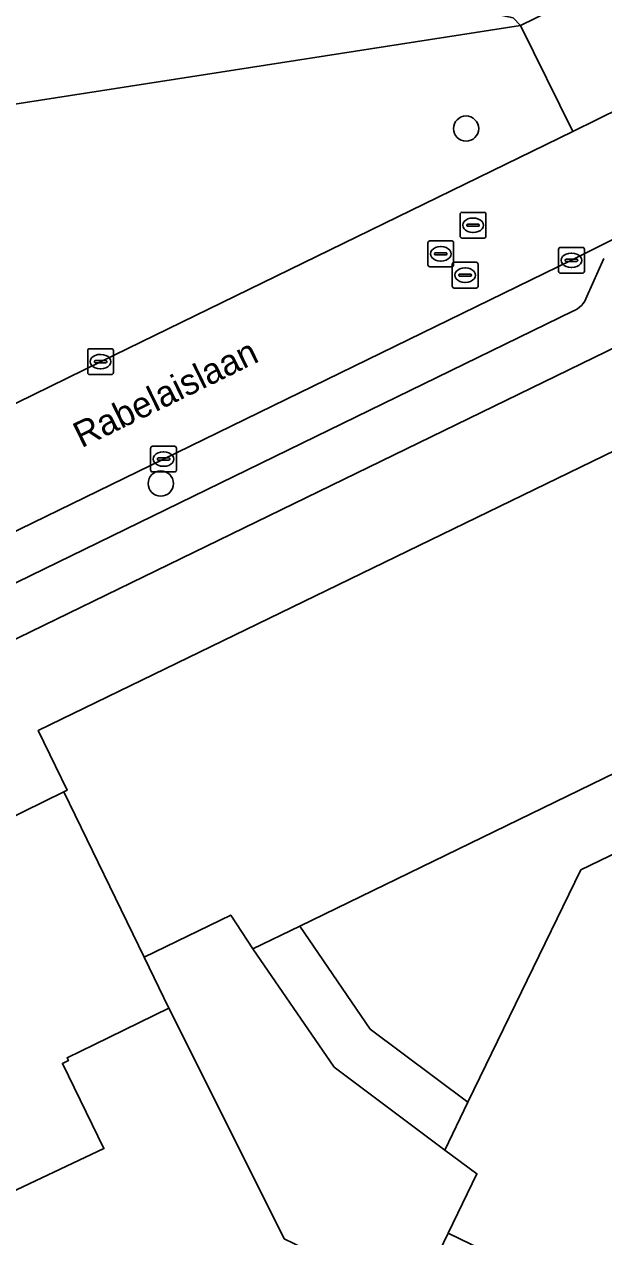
# Model space of a CAD drawing. Extents: x 160455 to 162082, y 388339 to 389736.
# Drawn here: x 160679.78 to 160702.27, y 388992.54 to 389039.61 of the extents above; entities that cross this region are included whole.
import ezdxf

# ---------------------------------------------------------------- set-up
doc = ezdxf.new("R2010")
doc.units = 0
for name, color, linetype in [('IMGEO_Boom', 7, 'Continuous'), ('IMGEO_Erf', 7, 'Continuous'), ('IMGEO_Groenvoorziening', 7, 'Continuous'), ('IMGEO_Kolk', 7, 'Continuous'), ('IMGEO_Openbare_ruimte_label', 7, 'Continuous'), ('IMGEO_Pand', 7, 'Continuous'), ('IMGEO_Pand_overbouw', 7, 'Continuous'), ('IMGEO_Parkeervlak_open', 7, 'Continuous'), ('IMGEO_Rijbaan_lokaal_gesloten', 7, 'Continuous'), ('IMGEO_Rioolput', 7, 'Continuous'), ('IMGEO_Voetpad_open', 7, 'Continuous')]:
    doc.layers.add(name, color=color, linetype=linetype)

msp = doc.modelspace()

# ---------------------------------------------------------------- linework, layer by layer
at = {"layer": 'IMGEO_Boom'}
for centre in [(160696.929, 389035.555), (160685.078, 389021.776)]:
    msp.add_circle(centre, 0.489, dxfattribs=at)
at = {"layer": 'IMGEO_Erf'}
for points in [[(160631.304, 389134.452), (160635.49, 389126.227), (160661.981, 389074.172), (160677.134, 389044.454), (160698.752, 389039.86), (160699.042, 389039.553), (160715.037, 389047.378)], [(160706.578, 389028.939), (160704.8, 389028.074), (160674.691, 389013.432), (160651.38, 389002.026)], [(160677.377, 389007.887), (160681.311, 389009.806), (160681.445, 389009.872), (160680.32, 389012.188), (160708.539, 389025.895)], [(160702.742, 389010.556), (160690.481, 389004.601), (160688.649, 389003.711), (160687.793, 389005.025), (160684.429, 389003.39), (160685.392, 389001.409), (160682.501, 389000), (160681.444, 388999.485), (160681.496, 388999.377), (160681.263, 388999.267), (160682.873, 388995.963), (160678.759, 388994.027), (160677.143, 388997.327), (160677.049, 388997.283), (160675.92, 388996.752), (160673.367, 388995.55), (160673.42, 388995.442), (160669.095, 388993.334), (160667.611, 388996.387), (160667.455, 388996.311), (160664.308, 388994.778), (160663.857, 388994.558), (160665.343, 388991.507)], [(160704.929, 388988.463), (160696.232, 388992.673), (160697.352, 388994.987), (160696.098, 388995.905), (160697.002, 388997.764), (160701.389, 389006.781), (160703.963, 389008.022)]]:
    msp.add_lwpolyline(points, dxfattribs=at)
at = {"layer": 'IMGEO_Groenvoorziening'}
for points in [[(160699.042, 389039.553), (160698.752, 389039.86), (160677.134, 389044.454), (160668.93, 389041.037), (160672.353, 389034.231), (160678.648, 389036.386)], [(160701.076, 389035.437), (160699.042, 389039.553), (160678.648, 389036.386), (160672.353, 389034.231), (160677.522, 389023.953), (160682.743, 389026.507)]]:
    msp.add_lwpolyline(points, close=True, dxfattribs=at)
at = {"layer": 'IMGEO_Kolk'}
for p, q in [((160700.519, 389030.016), (160700.519, 389030.868)), ((160700.594, 389030.942), (160701.446, 389030.942)), ((160701.52, 389030.868), (160701.52, 389030.016)), ((160700.778, 389030.436), (160700.778, 389030.448)), ((160701.216, 389030.399), (160700.818, 389030.399)), ((160700.821, 389030.485), (160701.219, 389030.485)), ((160701.007, 389030.722), (160701.032, 389030.722)), ((160701.262, 389030.448), (160701.262, 389030.436)), ((160701.446, 389029.942), (160700.594, 389029.942)), ((160701.03, 389030.162), (160701.005, 389030.162)), ((160682.242, 389026.083), (160682.242, 389026.935)), ((160682.317, 389027.009), (160683.169, 389027.009)), ((160682.73, 389026.789), (160682.755, 389026.789)), ((160683.243, 389026.935), (160683.243, 389026.083)), ((160682.501, 389026.503), (160682.501, 389026.515)), ((160682.939, 389026.466), (160682.541, 389026.466)), ((160682.544, 389026.552), (160682.942, 389026.552)), ((160682.753, 389026.229), (160682.728, 389026.229)), ((160682.985, 389026.515), (160682.985, 389026.503)), ((160683.169, 389026.009), (160682.317, 389026.009)), ((160684.686, 389022.3), (160684.686, 389023.152)), ((160684.761, 389023.226), (160685.613, 389023.226)), ((160685.174, 389023.006), (160685.199, 389023.006)), ((160685.687, 389023.152), (160685.687, 389022.3)), ((160684.945, 389022.72), (160684.945, 389022.732)), ((160685.383, 389022.683), (160684.985, 389022.683)), ((160684.988, 389022.769), (160685.386, 389022.769)), ((160685.197, 389022.446), (160685.172, 389022.446)), ((160685.429, 389022.732), (160685.429, 389022.72)), ((160685.613, 389022.226), (160684.761, 389022.226))]:
    msp.add_line(p, q, dxfattribs=at)
for points in [[(160700.519, 389030.016), (160700.519, 389030.868)], [(160700.594, 389030.942), (160701.446, 389030.942)], [(160701.52, 389030.868), (160701.52, 389030.016)], [(160701.446, 389029.942), (160700.594, 389029.942)], [(160682.242, 389026.083), (160682.242, 389026.935)], [(160682.317, 389027.009), (160683.169, 389027.009)], [(160683.243, 389026.935), (160683.243, 389026.083)], [(160683.169, 389026.009), (160682.317, 389026.009)], [(160684.686, 389022.3), (160684.686, 389023.152)], [(160684.761, 389023.226), (160685.613, 389023.226)], [(160685.687, 389023.152), (160685.687, 389022.3)], [(160685.613, 389022.226), (160684.761, 389022.226)]]:
    msp.add_lwpolyline(points, dxfattribs=at)
for centre, radius, start, end in [((160700.596, 389030.866), 0.0765, 91.552, 178.448), ((160700.596, 389030.866), 0.0765, 91.552, 178.448), ((160701.444, 389030.866), 0.0765, 1.552, 88.448), ((160701.444, 389030.866), 0.0765, 1.552, 88.448), ((160700.818, 389030.445), 0.0403, 85.8775, 175.7526), ((160700.815, 389030.435), 0.0366, 178.938, 274.7102), ((160701.219, 389030.442), 0.043, 264.8664, 352.4533), ((160701.223, 389030.447), 0.0386, 1.7309, 96.639), ((160700.596, 389030.018), 0.0765, 181.552, 268.448), ((160700.596, 389030.018), 0.0765, 181.552, 268.448), ((160701.444, 389030.018), 0.0765, 271.552, 358.448), ((160701.444, 389030.018), 0.0765, 271.552, 358.448), ((160682.319, 389026.933), 0.0765, 91.552, 178.448), ((160682.319, 389026.933), 0.0765, 91.552, 178.448), ((160683.167, 389026.933), 0.0765, 1.552, 88.448), ((160683.167, 389026.933), 0.0765, 1.552, 88.448), ((160682.541, 389026.512), 0.0403, 85.8775, 175.7526), ((160682.538, 389026.502), 0.0366, 178.938, 274.7102), ((160682.942, 389026.509), 0.043, 264.8664, 352.4533), ((160682.946, 389026.514), 0.0386, 1.7309, 96.639), ((160682.319, 389026.085), 0.0765, 181.552, 268.448), ((160682.319, 389026.085), 0.0765, 181.552, 268.448), ((160683.167, 389026.085), 0.0765, 271.552, 358.448), ((160683.167, 389026.085), 0.0765, 271.552, 358.448), ((160684.763, 389023.15), 0.0765, 91.552, 178.448), ((160684.763, 389023.15), 0.0765, 91.552, 178.448), ((160685.611, 389023.15), 0.0765, 1.552, 88.448), ((160685.611, 389023.15), 0.0765, 1.552, 88.448), ((160684.985, 389022.729), 0.0403, 85.8775, 175.7526), ((160684.982, 389022.719), 0.0366, 178.938, 274.7102), ((160685.386, 389022.726), 0.043, 264.8664, 352.4533), ((160685.39, 389022.731), 0.0386, 1.7309, 96.639), ((160684.763, 389022.302), 0.0765, 181.552, 268.448), ((160684.763, 389022.302), 0.0765, 181.552, 268.448), ((160685.611, 389022.302), 0.0765, 271.552, 358.448), ((160685.611, 389022.302), 0.0765, 271.552, 358.448)]:
    msp.add_arc(centre, radius, start, end, dxfattribs=at)
for centre, major_axis, ratio, start_param, end_param in [((160701.006, 389030.442), (-0.387, 0.002), 0.722429, 4.712389, 7.853982), ((160701.031, 389030.442), (-0.39, 0.002), 0.717154, 1.570796, 4.712389), ((160682.729, 389026.509), (-0.387, 0.002), 0.722429, 4.712389, 7.853982), ((160682.754, 389026.509), (-0.39, 0.002), 0.717154, 1.570796, 4.712389), ((160685.173, 389022.726), (-0.387, 0.002), 0.722429, 4.712389, 7.853982), ((160685.198, 389022.726), (-0.39, 0.002), 0.717154, 1.570796, 4.712389)]:
    msp.add_ellipse(centre, major_axis=major_axis, ratio=ratio, start_param=start_param, end_param=end_param, dxfattribs=at)
at = {"layer": 'IMGEO_Pand'}
for points in [[(160708.539, 389025.895), (160680.32, 389012.188), (160681.445, 389009.872), (160681.311, 389009.806), (160684.429, 389003.39), (160687.793, 389005.025), (160688.649, 389003.711), (160690.481, 389004.601), (160702.742, 389010.556)], [(160703.963, 389008.022), (160701.389, 389006.781), (160697.002, 388997.764), (160696.098, 388995.905), (160697.352, 388994.987), (160696.232, 388992.673), (160704.929, 388988.463)]]:
    msp.add_lwpolyline(points, dxfattribs=at)
msp.add_lwpolyline([(160684.429, 389003.39), (160681.311, 389009.806), (160677.377, 389007.887), (160676.85, 389008.967), (160672.516, 389006.856), (160673.039, 389005.779), (160675.845, 389000), (160677.143, 388997.327), (160678.759, 388994.027), (160682.873, 388995.963), (160681.263, 388999.267), (160681.496, 388999.377), (160681.444, 388999.485), (160682.501, 389000), (160685.392, 389001.409)], close=True, dxfattribs=at)
at = {"layer": 'IMGEO_Pand_overbouw'}
for points in [[(160684.429, 389003.39), (160685.392, 389001.409), (160686.098, 389000), (160689.872, 388992.464), (160690.248, 388992.282), (160694.941, 388990.006), (160696.232, 388992.673), (160704.929, 388988.463), (160710.543, 389000), (160710.81, 389000.549), (160710.52, 389000.682), (160710.382, 389000.382), (160709.341, 389002.516), (160712.043, 389003.818), (160711.916, 389003.546), (160712.208, 389003.41), (160712.515, 389004.079), (160717.865, 389006.688), (160708.539, 389025.895), (160680.32, 389012.188), (160681.445, 389009.872), (160681.311, 389009.806)], [(160688.649, 389003.711), (160691.804, 388999.127), (160696.098, 388995.905), (160697.002, 388997.764), (160693.202, 389000.599), (160690.481, 389004.601)]]:
    msp.add_lwpolyline(points, close=True, dxfattribs=at)
at = {"layer": 'IMGEO_Parkeervlak_open'}
for points in [[(160703.094, 389031.478), (160701.02, 389030.443), (160685.186, 389022.728), (160677.049, 389018.758), (160677.836, 389017.143), (160678.425, 389017.43), (160701.072, 389028.47)], [(160701.616, 389029.041), (160702.272, 389030.518)]]:
    msp.add_lwpolyline(points, dxfattribs=at)
msp.add_arc((160700.763, 389029.309), 0.895, 290.2358, 342.5385, dxfattribs=at)
at = {"layer": 'IMGEO_Rijbaan_lokaal_gesloten'}
msp.add_lwpolyline([(160714.541, 389042.026), (160702.958, 389036.375), (160701.076, 389035.437), (160682.743, 389026.507), (160677.522, 389023.953), (160676.085, 389023.25), (160666.163, 389018.396), (160649.541, 389010.262), (160648.994, 389010.023), (160650.975, 389005.988), (160651.2, 389006.091), (160657.413, 389009.132), (160661.027, 389010.901), (160665.679, 389013.179), (160668.435, 389014.528), (160669.054, 389014.834), (160673.065, 389016.814), (160673.354, 389016.955), (160677.049, 389018.758), (160685.186, 389022.728), (160701.02, 389030.443), (160703.094, 389031.478), (160703.377, 389031.619), (160720.813, 389040.138)], dxfattribs=at)
at = {"layer": 'IMGEO_Rioolput'}
for p, q in [((160696.698, 389031.378), (160696.698, 389032.23)), ((160696.773, 389032.304), (160697.625, 389032.304)), ((160697.699, 389032.23), (160697.699, 389031.378)), ((160696.957, 389031.798), (160696.957, 389031.81)), ((160697.395, 389031.761), (160696.997, 389031.761)), ((160697, 389031.847), (160697.398, 389031.847)), ((160697.186, 389032.084), (160697.211, 389032.084)), ((160697.441, 389031.81), (160697.441, 389031.798)), ((160697.625, 389031.304), (160696.773, 389031.304)), ((160697.209, 389031.524), (160697.184, 389031.524)), ((160695.445, 389030.267), (160695.445, 389031.119)), ((160695.52, 389031.193), (160696.372, 389031.193)), ((160695.933, 389030.973), (160695.958, 389030.973)), ((160696.446, 389031.119), (160696.446, 389030.267)), ((160695.704, 389030.687), (160695.704, 389030.699)), ((160696.142, 389030.65), (160695.744, 389030.65)), ((160695.747, 389030.736), (160696.145, 389030.736)), ((160695.956, 389030.413), (160695.931, 389030.413)), ((160696.188, 389030.699), (160696.188, 389030.687)), ((160696.467, 389030.366), (160697.319, 389030.366)), ((160696.372, 389030.193), (160695.52, 389030.193)), ((160696.392, 389029.44), (160696.392, 389030.292)), ((160696.651, 389029.86), (160696.651, 389029.872)), ((160696.694, 389029.909), (160697.092, 389029.909)), ((160696.88, 389030.146), (160696.905, 389030.146)), ((160697.135, 389029.872), (160697.135, 389029.86)), ((160697.393, 389030.292), (160697.393, 389029.44)), ((160697.089, 389029.823), (160696.691, 389029.823)), ((160696.903, 389029.586), (160696.878, 389029.586)), ((160697.319, 389029.366), (160696.467, 389029.366))]:
    msp.add_line(p, q, dxfattribs=at)
for points in [[(160696.698, 389031.378), (160696.698, 389032.23)], [(160696.773, 389032.304), (160697.625, 389032.304)], [(160697.699, 389032.23), (160697.699, 389031.378)], [(160697.625, 389031.304), (160696.773, 389031.304)], [(160695.445, 389030.267), (160695.445, 389031.119)], [(160695.52, 389031.193), (160696.372, 389031.193)], [(160696.446, 389031.119), (160696.446, 389030.267)], [(160696.467, 389030.366), (160697.319, 389030.366)], [(160696.372, 389030.193), (160695.52, 389030.193)], [(160696.392, 389029.44), (160696.392, 389030.292)], [(160697.393, 389030.292), (160697.393, 389029.44)], [(160697.319, 389029.366), (160696.467, 389029.366)]]:
    msp.add_lwpolyline(points, dxfattribs=at)
for centre, radius, start, end in [((160696.775, 389032.228), 0.0765, 91.552, 178.448), ((160696.775, 389032.228), 0.0765, 91.552, 178.448), ((160697.623, 389032.228), 0.0765, 1.552, 88.448), ((160697.623, 389032.228), 0.0765, 1.552, 88.448), ((160696.997, 389031.807), 0.0403, 85.8775, 175.7526), ((160696.994, 389031.797), 0.0366, 178.938, 274.7102), ((160697.398, 389031.804), 0.043, 264.8664, 352.4533), ((160697.402, 389031.809), 0.0386, 1.7309, 96.639), ((160696.775, 389031.38), 0.0765, 181.552, 268.448), ((160696.775, 389031.38), 0.0765, 181.552, 268.448), ((160697.623, 389031.38), 0.0765, 271.552, 358.448), ((160697.623, 389031.38), 0.0765, 271.552, 358.448), ((160695.522, 389031.117), 0.0765, 91.552, 178.448), ((160695.522, 389031.117), 0.0765, 91.552, 178.448), ((160696.37, 389031.117), 0.0765, 1.552, 88.448), ((160696.37, 389031.117), 0.0765, 1.552, 88.448), ((160695.744, 389030.696), 0.0403, 85.8775, 175.7526), ((160695.741, 389030.686), 0.0366, 178.938, 274.7102), ((160696.145, 389030.693), 0.043, 264.8664, 352.4533), ((160696.149, 389030.698), 0.0386, 1.7309, 96.639), ((160696.469, 389030.29), 0.0765, 91.552, 178.448), ((160696.469, 389030.29), 0.0765, 91.552, 178.448), ((160697.317, 389030.29), 0.0765, 1.552, 88.448), ((160697.317, 389030.29), 0.0765, 1.552, 88.448), ((160695.522, 389030.269), 0.0765, 181.552, 268.448), ((160695.522, 389030.269), 0.0765, 181.552, 268.448), ((160696.37, 389030.269), 0.0765, 271.552, 358.448), ((160696.37, 389030.269), 0.0765, 271.552, 358.448), ((160696.691, 389029.869), 0.0403, 85.8775, 175.7526), ((160697.096, 389029.871), 0.0386, 1.7309, 96.639), ((160696.469, 389029.442), 0.0765, 181.552, 268.448), ((160696.469, 389029.442), 0.0765, 181.552, 268.448), ((160696.688, 389029.859), 0.0366, 178.938, 274.7102), ((160697.092, 389029.866), 0.043, 264.8664, 352.4533), ((160697.317, 389029.442), 0.0765, 271.552, 358.448), ((160697.317, 389029.442), 0.0765, 271.552, 358.448)]:
    msp.add_arc(centre, radius, start, end, dxfattribs=at)
for centre, major_axis, ratio, start_param, end_param in [((160697.185, 389031.804), (-0.387, 0.002), 0.722429, 4.712389, 7.853982), ((160697.21, 389031.804), (-0.39, 0.002), 0.717154, 1.570796, 4.712389), ((160695.932, 389030.693), (-0.387, 0.002), 0.722429, 4.712389, 7.853982), ((160695.957, 389030.693), (-0.39, 0.002), 0.717154, 1.570796, 4.712389), ((160696.879, 389029.866), (-0.387, 0.002), 0.722429, 4.712389, 7.853982), ((160696.904, 389029.866), (-0.39, 0.002), 0.717154, 1.570796, 4.712389)]:
    msp.add_ellipse(centre, major_axis=major_axis, ratio=ratio, start_param=start_param, end_param=end_param, dxfattribs=at)
at = {"layer": 'IMGEO_Voetpad_open'}
for points in [[(160715.037, 389047.378), (160699.042, 389039.553), (160701.076, 389035.437), (160702.958, 389036.375), (160714.541, 389042.026)], [(160702.272, 389030.518), (160701.616, 389029.041)], [(160701.072, 389028.47), (160678.425, 389017.43), (160678.907, 389016.441), (160674.306, 389014.198), (160673.824, 389015.187), (160670.3, 389013.45), (160670.78, 389012.46), (160666.453, 389010.362), (160665.973, 389011.352), (160662.454, 389009.617), (160662.935, 389008.628), (160658.308, 389006.378), (160657.827, 389007.367), (160653.509, 389005.261)], [(160651.38, 389002.026), (160674.691, 389013.432), (160704.8, 389028.074)]]:
    msp.add_lwpolyline(points, dxfattribs=at)
msp.add_arc((160700.763, 389029.309), 0.895, 290.2358, 342.5385, dxfattribs=at)

# ---------------------------------------------------------------- texts
at = {"layer": 'IMGEO_Openbare_ruimte_label'}
msp.add_text('Rabelaislaan', height=1, rotation=26.0272, dxfattribs=at).set_placement((160682.002, 389023.142))

doc.saveas('drawing.dxf')
